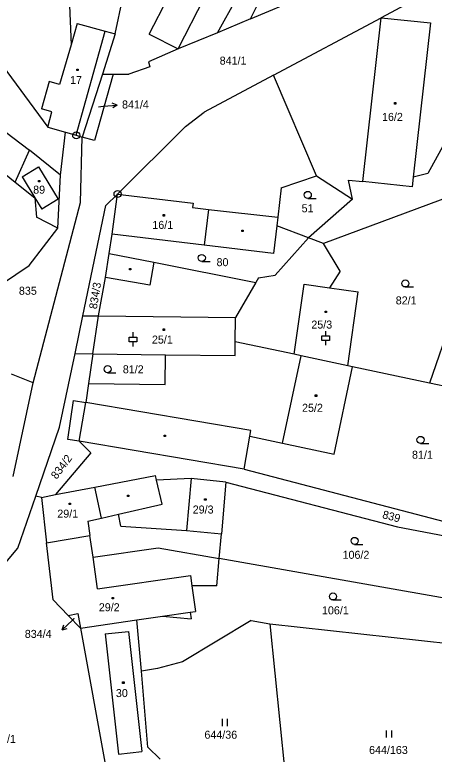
# Model space of a CAD drawing. Extents: x -791032 to -787751, y -1106872 to -1104403.
# Drawn here: x -789459.7 to -789370.7, y -1105520.6 to -1105363.5 of the extents above; entities that cross this region are included whole.
import ezdxf

# ---------------------------------------------------------------- set-up
doc = ezdxf.new("R2010")
doc.units = 0
for name, color, linetype in [('Komunikace', 7, 'Continuous'), ('Vrstva 1', 7, 'Continuous'), ('Vrstva 14', 7, 'Continuous'), ('Vrstva 15', 7, 'Continuous'), ('Vrstva 16', 7, 'Continuous'), ('Vrstva 2', 7, 'Continuous'), ('Vrstva 23', 7, 'Continuous'), ('Vrstva 25', 7, 'Continuous'), ('Vrstva 28', 7, 'Continuous')]:
    doc.layers.add(name, color=color, linetype=linetype)

msp = doc.modelspace()

# ---------------------------------------------------------------- linework, layer by layer
at = {"layer": 'Komunikace'}
for p, q in [((-789441.97, -1105383.07), (-789440.98, -1105382.98)), ((-789447.11, -1105491.77), (-789447.51, -1105492.15))]:
    msp.add_line(p, q, dxfattribs=at)
at = {"layer": 'Vrstva 1'}
for p, q in [((-789409.67, -1105364.4), (-789357.53, -1105342.45)), ((-789409.67, -1105364.4), (-789400.25, -1105345.18)), ((-789346.71, -1105345.3), (-789381.96, -1105364.16)), ((-789425.05, -1105370.8), (-789413.81, -1105348.8)), ((-789416.68, -1105367.39), (-789407.63, -1105351.13)), ((-789438.39, -1105367.62), (-789435.33, -1105352.87)), ((-789448.47, -1105353.39), (-789447.79, -1105369.91)), ((-789404.77, -1105376.36), (-789381.96, -1105364.16)), ((-789381.96, -1105364.16), (-789371.46, -1105365.23)), ((-789446.49, -1105365.4), (-789447.79, -1105369.91)), ((-789446.49, -1105365.4), (-789440.54, -1105367.03)), ((-789409.67, -1105364.4), (-789416.68, -1105367.39)), ((-789371.46, -1105365.23), (-789375.14, -1105398.04)), ((-789468.52, -1105366.04), (-789452.74, -1105387.39)), ((-789440.54, -1105367.03), (-789438.39, -1105367.62)), ((-789416.68, -1105367.39), (-789425.05, -1105370.8)), ((-789438.39, -1105367.62), (-789441.14, -1105376.19)), ((-789447.79, -1105369.91), (-789450.23, -1105378.35)), ((-789357.5, -1105370.6), (-789371.98, -1105397.25)), ((-789425.05, -1105370.8), (-789431.36, -1105373.53)), ((-789431.36, -1105373.53), (-789431.04, -1105374.59)), ((-789431.04, -1105374.59), (-789435.52, -1105376.15)), ((-789441.14, -1105376.19), (-789445.41, -1105389.53)), ((-789438.84, -1105376.17), (-789442.8, -1105390.27)), ((-789441.14, -1105376.19), (-789438.84, -1105376.17)), ((-789438.84, -1105376.17), (-789435.52, -1105376.15)), ((-789404.77, -1105376.36), (-789419.52, -1105384.25)), ((-789395.68, -1105397.78), (-789404.77, -1105376.36)), ((-789452.46, -1105377.72), (-789454.09, -1105383.51)), ((-789450.23, -1105378.35), (-789452.46, -1105377.72)), ((-789468.96, -1105382.96), (-789456.6, -1105392.29)), ((-789451.84, -1105384.14), (-789454.09, -1105383.51)), ((-789452.74, -1105387.39), (-789451.84, -1105384.14)), ((-789423.48, -1105387.27), (-789419.52, -1105384.25)), ((-789452.74, -1105387.39), (-789448.95, -1105388.5)), ((-789437.94, -1105401.63), (-789423.48, -1105387.27)), ((-789472.06, -1105389.13), (-789459.64, -1105399.07)), ((-789450.02, -1105397.62), (-789448.95, -1105388.5)), ((-789448.95, -1105388.5), (-789446.71, -1105389.15)), ((-789446.71, -1105389.15), (-789445.41, -1105389.53)), ((-789445.76, -1105403.45), (-789445.41, -1105389.53)), ((-789442.8, -1105390.27), (-789445.41, -1105389.53)), ((-789459.64, -1105399.07), (-789456.6, -1105392.29)), ((-789450.02, -1105397.62), (-789456.6, -1105392.29)), ((-789371.98, -1105397.25), (-789375.14, -1105398.04)), ((-789450.63, -1105408.86), (-789450.02, -1105397.62)), ((-789403.16, -1105400.34), (-789395.68, -1105397.78)), ((-789395.68, -1105397.78), (-789388.04, -1105402.73)), ((-789388.9, -1105398.65), (-789385.8, -1105398.99)), ((-789388.04, -1105402.73), (-789388.9, -1105398.65)), ((-789375.14, -1105398.04), (-789375.37, -1105400.12)), ((-789459.64, -1105399.07), (-789455.45, -1105402.42)), ((-789403.16, -1105400.34), (-789403.89, -1105406.54)), ((-789375.37, -1105400.12), (-789385.8, -1105398.99)), ((-789440.39, -1105404.05), (-789437.94, -1105401.63)), ((-789439.08, -1105410.17), (-789437.94, -1105401.63)), ((-789366.67, -1105401.92), (-789394.2, -1105412.1)), ((-789455.86, -1105441.72), (-789445.76, -1105403.45)), ((-789455.45, -1105402.42), (-789455.15, -1105406.53)), ((-789388.04, -1105402.73), (-789397.38, -1105410.91)), ((-789445.27, -1105427.47), (-789440.39, -1105404.05)), ((-789450.63, -1105408.86), (-789455.15, -1105406.53)), ((-789403.89, -1105406.54), (-789404.11, -1105408.4)), ((-789360.03, -1105407.78), (-789371.65, -1105441.77)), ((-789456.67, -1105416.81), (-789450.63, -1105408.86)), ((-789404.11, -1105408.4), (-789404.82, -1105414.25)), ((-789397.38, -1105410.91), (-789404.11, -1105408.4)), ((-789439.71, -1105414.24), (-789439.08, -1105410.17)), ((-789419.51, -1105412.5), (-789439.08, -1105410.17)), ((-789404.41, -1105418.87), (-789397.38, -1105410.91)), ((-789394.2, -1105412.1), (-789397.38, -1105410.91)), ((-789404.82, -1105414.25), (-789419.51, -1105412.5)), ((-789390.65, -1105417.98), (-789394.2, -1105412.1)), ((-789440.5, -1105419.34), (-789439.71, -1105414.24)), ((-789439.71, -1105414.24), (-789430.24, -1105416.12)), ((-789430.24, -1105416.12), (-789408.55, -1105420.43)), ((-789462.38, -1105420.65), (-789456.67, -1105416.81)), ((-789407.95, -1105419.4), (-789404.41, -1105418.87)), ((-789390.65, -1105417.98), (-789392.91, -1105421.54)), ((-789441.93, -1105427.51), (-789440.5, -1105419.34)), ((-789408.55, -1105420.43), (-789412.86, -1105427.86)), ((-789407.95, -1105419.4), (-789408.55, -1105420.43)), ((-789392.91, -1105421.54), (-789386.81, -1105422.4)), ((-789389.02, -1105438.09), (-789386.81, -1105422.4)), ((-789446.95, -1105435.52), (-789445.27, -1105427.47)), ((-789445.27, -1105427.47), (-789441.93, -1105427.51)), ((-789412.92, -1105433), (-789412.86, -1105427.86)), ((-789412.96, -1105435.93), (-789412.92, -1105433)), ((-789400.39, -1105435.67), (-789412.92, -1105433)), ((-789450.21, -1105451.15), (-789446.95, -1105435.52)), ((-789446.95, -1105435.52), (-789443.16, -1105435.57)), ((-789443.16, -1105435.57), (-789444.07, -1105441.86)), ((-789443.16, -1105435.57), (-789427.7, -1105435.76)), ((-789427.78, -1105442.06), (-789427.7, -1105435.76)), ((-789427.7, -1105435.76), (-789412.96, -1105435.93)), ((-789398.93, -1105435.98), (-789400.39, -1105435.67)), ((-789389.02, -1105438.09), (-789398.93, -1105435.98)), ((-789387.98, -1105438.32), (-789389.02, -1105438.09)), ((-789391.93, -1105456.85), (-789387.98, -1105438.32)), ((-789371.65, -1105441.77), (-789387.98, -1105438.32)), ((-789455.86, -1105441.72), (-789460.46, -1105439.89)), ((-789460.1, -1105461.61), (-789455.86, -1105441.72)), ((-789444.07, -1105441.86), (-789444.65, -1105445.89)), ((-789444.07, -1105441.86), (-789427.78, -1105442.06)), ((-789351.15, -1105446.16), (-789371.65, -1105441.77)), ((-789448.44, -1105453.74), (-789447.24, -1105445.45)), ((-789447.24, -1105445.45), (-789444.65, -1105445.89)), ((-789455.27, -1105465.77), (-789450.21, -1105451.15)), ((-789446.05, -1105454.11), (-789448.44, -1105453.74)), ((-789411.01, -1105460.08), (-789409.8, -1105453.04)), ((-789409.8, -1105453.04), (-789402.88, -1105454.52)), ((-789446.05, -1105454.11), (-789443.61, -1105456.62)), ((-789411.01, -1105460.08), (-789446.05, -1105454.11)), ((-789402.88, -1105454.52), (-789391.93, -1105456.85)), ((-789443.61, -1105456.62), (-789451.11, -1105465.48)), ((-789411.01, -1105460.08), (-789361.97, -1105472.94)), ((-789442.73, -1105463.86), (-789429.89, -1105461.38)), ((-789429.65, -1105462.42), (-789429.89, -1105461.38)), ((-789422.27, -1105462.03), (-789429.65, -1105462.42)), ((-789414.89, -1105462.8), (-789422.27, -1105462.03)), ((-789414.89, -1105462.8), (-789415.86, -1105473.78)), ((-789414.89, -1105462.8), (-789378.46, -1105472.29)), ((-789451.11, -1105465.48), (-789442.73, -1105463.86)), ((-789441.29, -1105470.48), (-789442.73, -1105463.86)), ((-789459.11, -1105476.85), (-789455.27, -1105465.77)), ((-789454.1, -1105466.06), (-789455.27, -1105465.77)), ((-789454.1, -1105466.06), (-789451.11, -1105465.48)), ((-789454.1, -1105466.06), (-789452.99, -1105475.7)), ((-789441.29, -1105470.48), (-789437.72, -1105469.65)), ((-789437.23, -1105472.17), (-789437.72, -1105469.65)), ((-789437.23, -1105472.17), (-789423.25, -1105473.13)), ((-789378.46, -1105472.29), (-789357.82, -1105476.28)), ((-789452.99, -1105475.7), (-789443.78, -1105474.14)), ((-789443.11, -1105478.76), (-789443.78, -1105474.14)), ((-789423.25, -1105473.13), (-789415.86, -1105473.78)), ((-789416.33, -1105479.05), (-789415.86, -1105473.78)), ((-789451.61, -1105487.82), (-789452.99, -1105475.7)), ((-789472.97, -1105493.34), (-789459.11, -1105476.85)), ((-789443.11, -1105478.76), (-789429.29, -1105476.77)), ((-789429.29, -1105476.77), (-789416.33, -1105479.05)), ((-789416.84, -1105484.88), (-789416.33, -1105479.05)), ((-789354.56, -1105489.92), (-789416.33, -1105479.05)), ((-789422.13, -1105484.85), (-789421.34, -1105490.28)), ((-789416.84, -1105484.88), (-789422.13, -1105484.85)), ((-789448.39, -1105491.13), (-789451.61, -1105487.82)), ((-789448.39, -1105491.13), (-789446.34, -1105490.76)), ((-789445.79, -1105493.81), (-789448.39, -1105491.13)), ((-789446.34, -1105490.76), (-789445.79, -1105493.81)), ((-789433.79, -1105492.08), (-789428.37, -1105491.3)), ((-789428.37, -1105491.3), (-789422.28, -1105491.89)), ((-789422.49, -1105490.45), (-789421.34, -1105490.28)), ((-789422.49, -1105490.45), (-789422.28, -1105491.89)), ((-789445.79, -1105493.81), (-789433.79, -1105492.08)), ((-789432.85, -1105503.01), (-789433.79, -1105492.08)), ((-789409.57, -1105492.24), (-789424.13, -1105501.02)), ((-789409.57, -1105492.24), (-789405.54, -1105492.93)), ((-789405.54, -1105492.93), (-789400.71, -1105541.35)), ((-789405.54, -1105492.93), (-789355.33, -1105498.49)), ((-789445.79, -1105493.81), (-789440.46, -1105523.11)), ((-789429.42, -1105502.43), (-789432.85, -1105503.01)), ((-789424.13, -1105501.02), (-789429.42, -1105502.43)), ((-789431.48, -1105519.09), (-789432.85, -1105503.01)), ((-789428.84, -1105521.69), (-789431.48, -1105519.09))]:
    msp.add_line(p, q, dxfattribs=at)
at = {"layer": 'Vrstva 16'}
for p, q in [((-789440.98, -1105382.98), (-789437.991, -1105382.72)), ((-789437.991, -1105382.72), (-789439.03, -1105382.308)), ((-789437.991, -1105382.72), (-789438.944, -1105383.304)), ((-789447.51, -1105492.15), (-789449.689, -1105494.211)), ((-789449.689, -1105494.211), (-789449.306, -1105493.16)), ((-789449.689, -1105494.211), (-789448.619, -1105493.887))]:
    msp.add_line(p, q, dxfattribs=at)
at = {"layer": 'Vrstva 2'}
for p, q in [((-789431.19, -1105367.66), (-789419.96, -1105345.66)), ((-789385.8, -1105398.99), (-789381.96, -1105364.16)), ((-789446.71, -1105389.15), (-789440.54, -1105367.03)), ((-789431.19, -1105367.66), (-789425.05, -1105370.8)), ((-789458.17, -1105397.94), (-789454.69, -1105395.84)), ((-789454.69, -1105395.84), (-789450.53, -1105402.73)), ((-789458.17, -1105397.94), (-789455.45, -1105402.42)), ((-789437.94, -1105401.63), (-789421.88, -1105403.55)), ((-789455.45, -1105402.42), (-789454, -1105404.82)), ((-789450.53, -1105402.73), (-789454, -1105404.82)), ((-789421.88, -1105403.55), (-789421.97, -1105404.51)), ((-789421.97, -1105404.51), (-789418.6, -1105404.89)), ((-789418.6, -1105404.89), (-789419.51, -1105412.5)), ((-789418.6, -1105404.89), (-789403.89, -1105406.54)), ((-789430.24, -1105416.12), (-789431.09, -1105420.99)), ((-789431.09, -1105420.99), (-789440.5, -1105419.34)), ((-789400.39, -1105435.67), (-789398.29, -1105420.78)), ((-789398.29, -1105420.78), (-789392.91, -1105421.54)), ((-789443.16, -1105435.57), (-789441.93, -1105427.51)), ((-789441.93, -1105427.51), (-789412.86, -1105427.86)), ((-789402.88, -1105454.52), (-789398.93, -1105435.98)), ((-789446.05, -1105454.11), (-789444.65, -1105445.89)), ((-789409.6, -1105451.86), (-789444.65, -1105445.89)), ((-789409.8, -1105453.04), (-789409.6, -1105451.86)), ((-789428.47, -1105467.51), (-789429.65, -1105462.42)), ((-789422.27, -1105462.03), (-789423.25, -1105473.13)), ((-789437.72, -1105469.65), (-789428.47, -1105467.51)), ((-789444.21, -1105471.15), (-789441.29, -1105470.48)), ((-789444.21, -1105471.15), (-789443.78, -1105474.14)), ((-789442.14, -1105485.5), (-789443.11, -1105478.76)), ((-789442.14, -1105485.5), (-789422.44, -1105482.66)), ((-789422.44, -1105482.66), (-789422.13, -1105484.85)), ((-789428.37, -1105491.3), (-789422.49, -1105490.45)), ((-789440.53, -1105495.07), (-789435.56, -1105494.52)), ((-789435.56, -1105494.52), (-789432.76, -1105520.07)), ((-789440.53, -1105495.07), (-789437.73, -1105520.61)), ((-789437.73, -1105520.61), (-789432.76, -1105520.07))]:
    msp.add_line(p, q, dxfattribs=at)
at = {"layer": 'Vrstva 23'}
for p, q in [((-789397.51, -1105402.55), (-789395.76, -1105402.55)), ((-789420.02, -1105415.95), (-789418.27, -1105415.95)), ((-789376.8, -1105421.37), (-789375.05, -1105421.37)), ((-789434.62, -1105432), (-789434.62, -1105431)), ((-789394.5, -1105432.76), (-789394.5, -1105431.76)), ((-789394.5, -1105431.76), (-789392.9, -1105431.76)), ((-789393.7, -1105431.76), (-789393.7, -1105430.76)), ((-789392.9, -1105431.76), (-789392.9, -1105432.76)), ((-789435.42, -1105433), (-789435.42, -1105432)), ((-789435.42, -1105432), (-789433.82, -1105432)), ((-789433.82, -1105433), (-789435.42, -1105433)), ((-789434.62, -1105434), (-789434.62, -1105433)), ((-789433.82, -1105432), (-789433.82, -1105433)), ((-789392.9, -1105432.76), (-789394.5, -1105432.76)), ((-789393.7, -1105433.76), (-789393.7, -1105432.76)), ((-789440.03, -1105439.57), (-789438.28, -1105439.57)), ((-789373.57, -1105454.6), (-789371.82, -1105454.6)), ((-789387.57, -1105476.06), (-789385.82, -1105476.06)), ((-789392.16, -1105487.85), (-789390.41, -1105487.85)), ((-789415.62, -1105514.63), (-789415.62, -1105513.13)), ((-789414.62, -1105513.13), (-789414.62, -1105514.63)), ((-789380.76, -1105517.07), (-789380.76, -1105515.57)), ((-789379.76, -1105515.57), (-789379.76, -1105517.07))]:
    msp.add_line(p, q, dxfattribs=at)
for centre in [(-789397.51, -1105401.8), (-789420.02, -1105415.2), (-789376.8, -1105420.62), (-789440.03, -1105438.82), (-789373.57, -1105453.85), (-789387.57, -1105475.31), (-789392.16, -1105487.1)]:
    msp.add_circle(centre, 0.75, dxfattribs=at)
at = {"layer": 'Vrstva 25'}
for p, q in [((-789446.58, -1105375.11), (-789446.28, -1105375.11)), ((-789446.58, -1105375.41), (-789446.58, -1105375.11)), ((-789446.28, -1105375.11), (-789446.28, -1105375.41)), ((-789446.28, -1105375.41), (-789446.58, -1105375.41)), ((-789379.12, -1105382.21), (-789378.82, -1105382.21)), ((-789379.12, -1105382.51), (-789379.12, -1105382.21)), ((-789378.82, -1105382.51), (-789379.12, -1105382.51)), ((-789378.82, -1105382.21), (-789378.82, -1105382.51)), ((-789454.7, -1105398.75), (-789454.4, -1105398.75)), ((-789454.7, -1105399.05), (-789454.7, -1105398.75)), ((-789454.4, -1105398.75), (-789454.4, -1105399.05)), ((-789454.4, -1105399.05), (-789454.7, -1105399.05)), ((-789428.25, -1105405.99), (-789427.95, -1105405.99)), ((-789428.25, -1105406.29), (-789428.25, -1105405.99)), ((-789427.95, -1105406.29), (-789428.25, -1105406.29)), ((-789427.95, -1105405.99), (-789427.95, -1105406.29)), ((-789411.51, -1105409.31), (-789411.21, -1105409.31)), ((-789411.51, -1105409.61), (-789411.51, -1105409.31)), ((-789411.21, -1105409.61), (-789411.51, -1105409.61)), ((-789411.21, -1105409.31), (-789411.21, -1105409.61)), ((-789435.38, -1105417.46), (-789435.08, -1105417.46)), ((-789435.38, -1105417.76), (-789435.38, -1105417.46)), ((-789435.08, -1105417.46), (-789435.08, -1105417.76)), ((-789435.08, -1105417.76), (-789435.38, -1105417.76)), ((-789393.83, -1105426.52), (-789393.53, -1105426.52)), ((-789393.83, -1105426.82), (-789393.83, -1105426.52)), ((-789393.53, -1105426.82), (-789393.83, -1105426.82)), ((-789393.53, -1105426.52), (-789393.53, -1105426.82)), ((-789428.26, -1105430.29), (-789427.96, -1105430.29)), ((-789428.26, -1105430.59), (-789428.26, -1105430.29)), ((-789427.96, -1105430.29), (-789427.96, -1105430.59)), ((-789427.96, -1105430.59), (-789428.26, -1105430.59)), ((-789395.91, -1105444.3), (-789395.61, -1105444.3)), ((-789395.91, -1105444.6), (-789395.91, -1105444.3)), ((-789395.61, -1105444.3), (-789395.61, -1105444.6)), ((-789395.61, -1105444.6), (-789395.91, -1105444.6)), ((-789428.04, -1105452.82), (-789427.74, -1105452.82)), ((-789428.04, -1105453.12), (-789428.04, -1105452.82)), ((-789427.74, -1105453.12), (-789428.04, -1105453.12)), ((-789427.74, -1105452.82), (-789427.74, -1105453.12)), ((-789435.82, -1105465.59), (-789435.52, -1105465.59)), ((-789435.82, -1105465.89), (-789435.82, -1105465.59)), ((-789435.52, -1105465.89), (-789435.82, -1105465.89)), ((-789435.52, -1105465.59), (-789435.52, -1105465.89)), ((-789419.42, -1105466.36), (-789419.12, -1105466.36)), ((-789419.42, -1105466.66), (-789419.42, -1105466.36)), ((-789419.12, -1105466.36), (-789419.12, -1105466.66)), ((-789448.18, -1105467.26), (-789447.88, -1105467.26)), ((-789448.18, -1105467.56), (-789448.18, -1105467.26)), ((-789447.88, -1105467.56), (-789448.18, -1105467.56)), ((-789447.88, -1105467.26), (-789447.88, -1105467.56)), ((-789419.12, -1105466.66), (-789419.42, -1105466.66)), ((-789439.08, -1105487.32), (-789438.78, -1105487.32)), ((-789439.08, -1105487.62), (-789439.08, -1105487.32)), ((-789438.78, -1105487.62), (-789439.08, -1105487.62)), ((-789438.78, -1105487.32), (-789438.78, -1105487.62)), ((-789436.83, -1105505.27), (-789436.53, -1105505.27)), ((-789436.83, -1105505.57), (-789436.83, -1105505.27)), ((-789436.53, -1105505.57), (-789436.83, -1105505.57)), ((-789436.53, -1105505.27), (-789436.53, -1105505.57))]:
    msp.add_line(p, q, dxfattribs=at)
at = {"layer": 'Vrstva 28'}
for centre, radius in [((-789446.69, -1105389.15), 0.75), ((-789446.69, -1105389.15), 0.01), ((-789437.91, -1105401.62), 0.75), ((-789437.91, -1105401.62), 0.01)]:
    msp.add_circle(centre, radius, dxfattribs=at)

# ---------------------------------------------------------------- texts
at = {"layer": 'Vrstva 14'}
for s, height, p in [('841/1', 1.7, (-789416.222, -1105374.13)), ('841/4', 0.1, (-789441.97, -1105383.07)), ('51', 1.7, (-789398.816, -1105405.5)), ('80', 1.7, (-789416.886, -1105416.95)), ('835', 1.7, (-789458.863, -1105423.02)), ('82/1', 1.7, (-789378.833, -1105425.07)), ('81/2', 1.7, (-789436.793, -1105439.7)), ('81/1', 1.7, (-789375.376, -1105457.85)), ('106/2', 1.7, (-789390.122, -1105479.11)), ('106/1', 1.7, (-789394.496, -1105490.91)), ('834/4', 0.1, (-789447.313, -1105491.77)), ('834/1', 1.7, (-789465.189, -1105518.22)), ('644/36', 1.7, (-789419.462, -1105517.33)), ('644/163', 1.7, (-789384.495, -1105520.57))]:
    msp.add_text(s, height=height, dxfattribs=at).set_placement(p)
for s, rotation, p in [('834/3', 80.67042, (-789442.315, -1105426.15)), ('834/2', 53.22096, (-789450.855, -1105462.336)), ('839', 345.06855, (-789381.792, -1105470.438))]:
    msp.add_text(s, height=1.7, rotation=rotation, dxfattribs=at).set_placement(p)
at = {"layer": 'Vrstva 15'}
for s, p in [('17', (-789447.997, -1105378.25)), ('16/2', (-789381.743, -1105386.09)), ('89', (-789455.837, -1105401.55)), ('16/1', (-789430.527, -1105409.03)), ('25/3', (-789396.756, -1105430.2)), ('25/1', (-789430.609, -1105433.39)), ('25/2', (-789398.726, -1105447.88)), ('29/3', (-789421.95, -1105469.49)), ('29/1', (-789450.713, -1105470.37)), ('29/2', (-789441.89, -1105490.25)), ('30', (-789438.266, -1105508.48))]:
    msp.add_text(s, height=1.7, dxfattribs=at).set_placement(p)
at = {"layer": 'Vrstva 16'}
for s, p in [('841/4', (-789436.96, -1105383.45)), ('834/4', (-789457.613, -1105495.91))]:
    msp.add_text(s, height=1.7, dxfattribs=at).set_placement(p)

doc.saveas('drawing.dxf')
